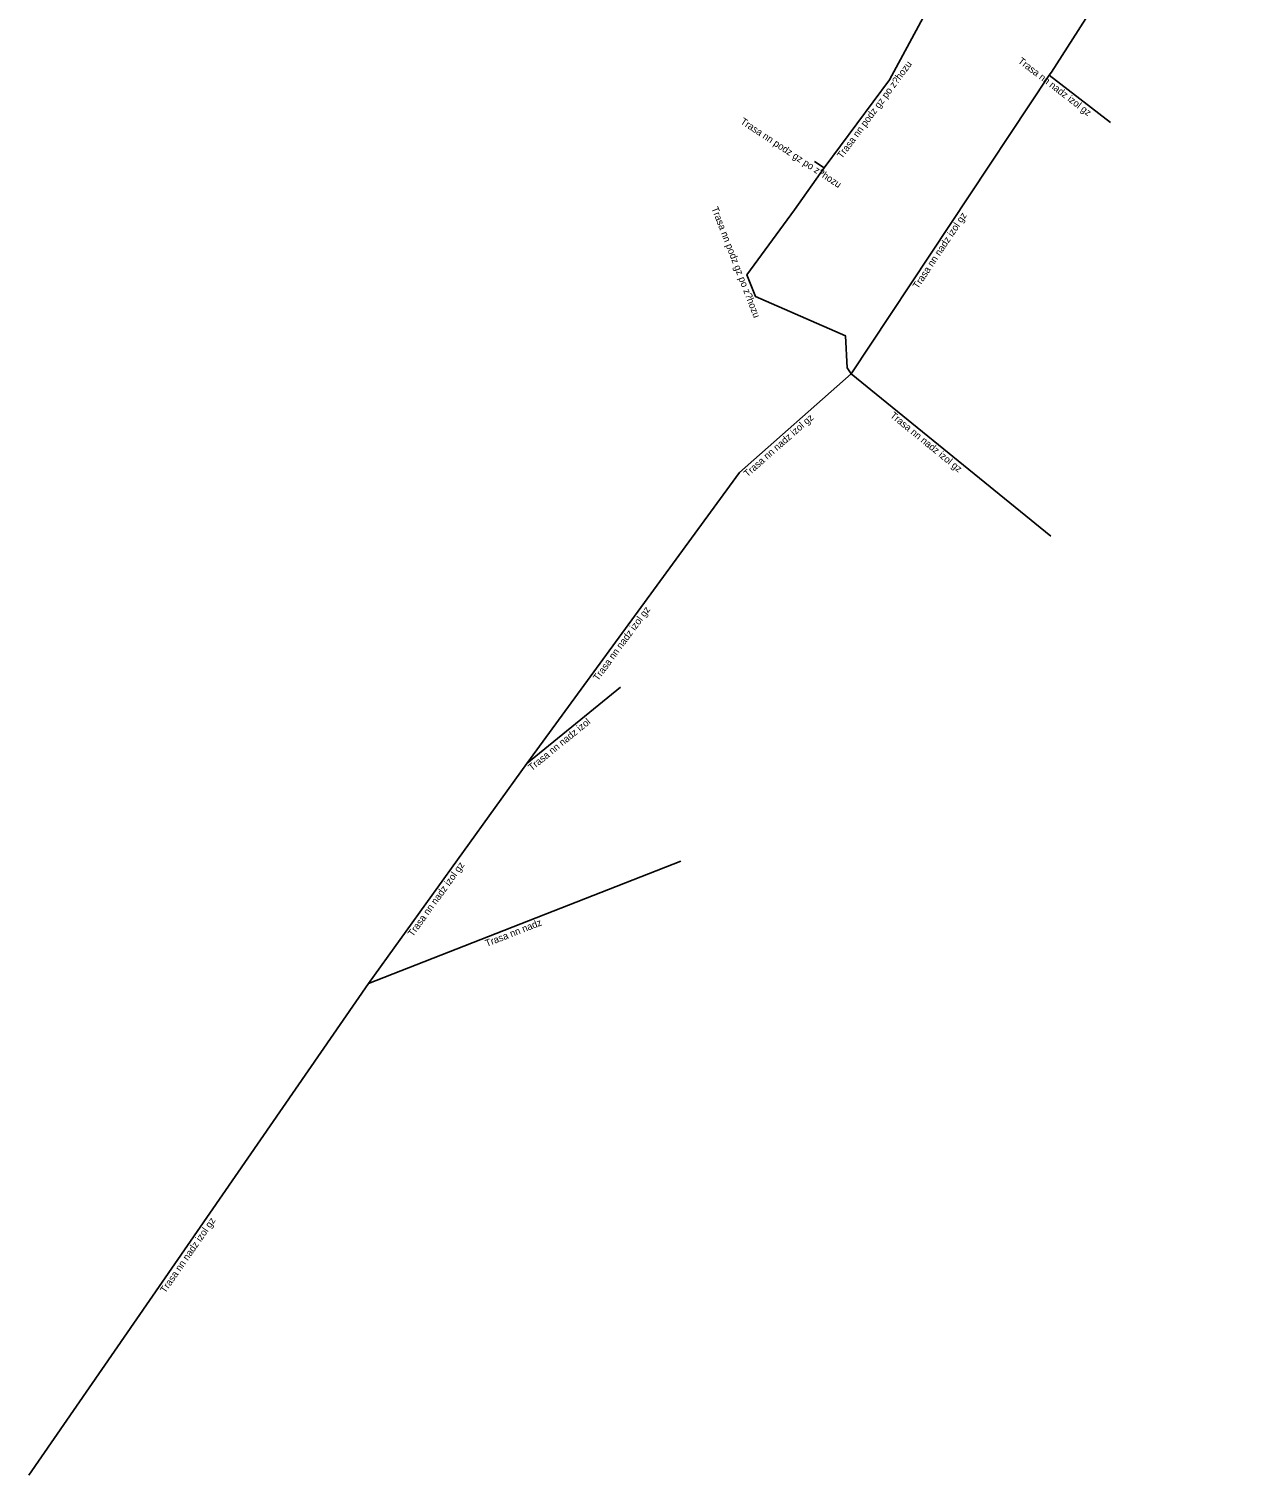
# Model space of a CAD drawing. Extents: x -770668 to -770481, y -1049958 to -1049459.
# Drawn here: x -770624.1 to -770536.4, y -1049958.3 to -1049855.1 of the extents above; entities that cross this region are included whole.
import ezdxf

# ---------------------------------------------------------------- set-up
doc = ezdxf.new("R2010")
doc.units = 0
doc.layers.add('Popiskový text - Ostatní atributy Trasy', color=7, linetype='Continuous')
doc.layers.add('Spojnice NN', color=7, linetype='Continuous')

msp = doc.modelspace()

# ---------------------------------------------------------------- linework, layer by layer
at = {"layer": 'Spojnice NN'}
for points in [[(-770536.43, -1049835.1), (-770551.17, -1049858.17), (-770551.32, -1049858.4)], [(-770567.38, -1049865.01), (-770562.73, -1049858.73), (-770559.69, -1049853.14), (-770559.51, -1049852.07)], [(-770551.32, -1049858.4), (-770565.45, -1049879.69)], [(-770551.32, -1049858.4), (-770546.95, -1049861.76)], [(-770568.06, -1049864.56), (-770567.38, -1049865.01)], [(-770565.45, -1049879.69), (-770565.73, -1049879.27), (-770565.85, -1049876.99), (-770572.29, -1049874.19), (-770572.89, -1049872.64), (-770569.49, -1049867.99), (-770567.38, -1049865.01)], [(-770573.41, -1049886.73), (-770565.45, -1049879.69)], [(-770565.45, -1049879.69), (-770551.21, -1049891.29)], [(-770573.41, -1049886.73), (-770588.6, -1049907.51)], [(-770588.6, -1049907.51), (-770581.9, -1049902.06)], [(-770599.89, -1049923.2), (-770588.6, -1049907.51)], [(-770599.89, -1049923.2), (-770577.61, -1049914.48)], [(-770624.1, -1049958.27), (-770599.89, -1049923.2)]]:
    msp.add_lwpolyline(points, dxfattribs=at)

# ---------------------------------------------------------------- texts
at = {"layer": 'Popiskový text - Ostatní atributy Trasy'}
for s, rotation, p in [('Trasa nn nadz izol gz', 322.4662, (-770553.6, -1049857.47)), ('Trasa nn podz gz po z?hozu', 53.4821, (-770566.11, -1049864.39)), ('Trasa nn podz gz po z?hozu', 326.5048, (-770573.4, -1049861.81)), ('Trasa nn podz gz po z?hozu', 291.1613, (-770575.43, -1049867.89)), ('Trasa nn nadz izol gz', 56.4371, (-770560.69, -1049873.68)), ('Trasa nn nadz izol gz', 41.4791, (-770572.85, -1049887.1)), ('Trasa nn nadz izol gz', 320.8335, (-770562.72, -1049882.75)), ('Trasa nn nadz izol gz', 53.8384, (-770583.51, -1049901.65)), ('Trasa nn nadz izol', 39.1659, (-770588.24, -1049908.06)), ('Trasa nn nadz izol gz', 54.2625, (-770596.72, -1049919.9)), ('Trasa nn nadz', 21.3878, (-770591.45, -1049920.59)), ('Trasa nn nadz izol gz', 55.3751, (-770614.38, -1049945.33))]:
    msp.add_text(s, height=0.5, rotation=rotation, dxfattribs=at).set_placement(p)

doc.saveas('drawing.dxf')
